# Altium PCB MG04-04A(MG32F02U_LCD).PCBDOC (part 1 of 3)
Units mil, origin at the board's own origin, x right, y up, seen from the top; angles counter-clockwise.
Board outline 5905.51 x 3543.31 mil, 2 copper layers (Top Layer, Bottom Layer); 293 components, 227 nets, 959 pads, 508 vias.
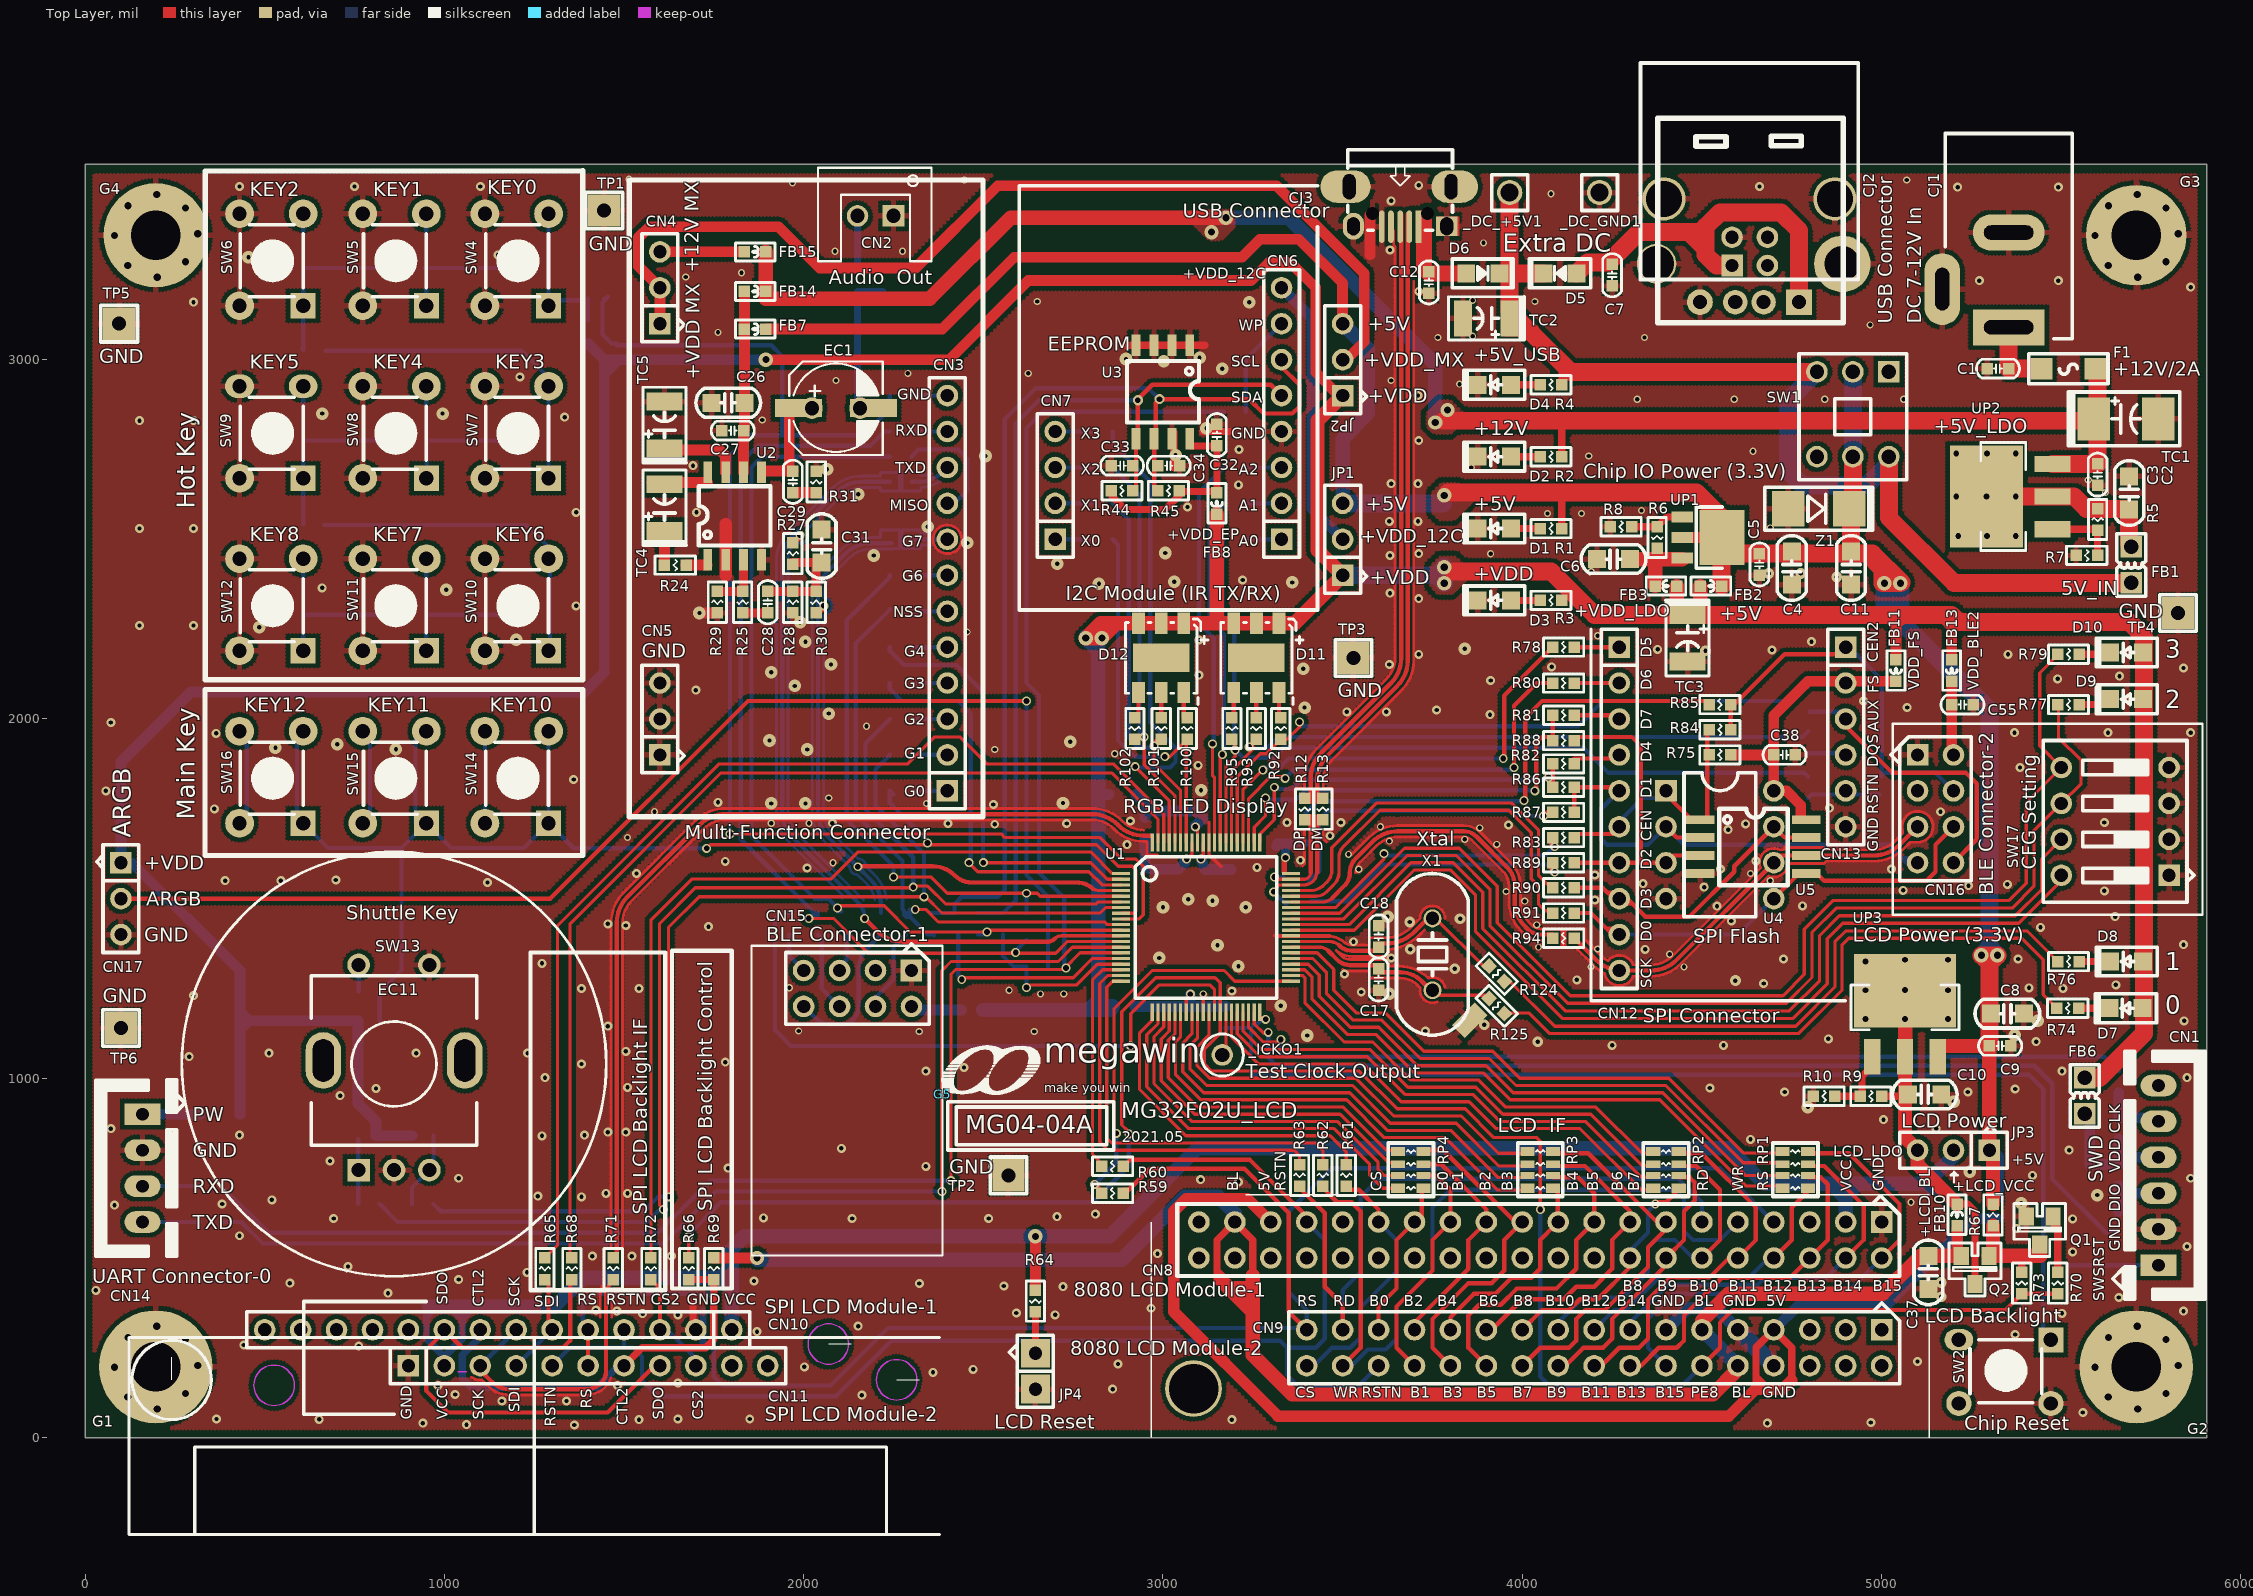
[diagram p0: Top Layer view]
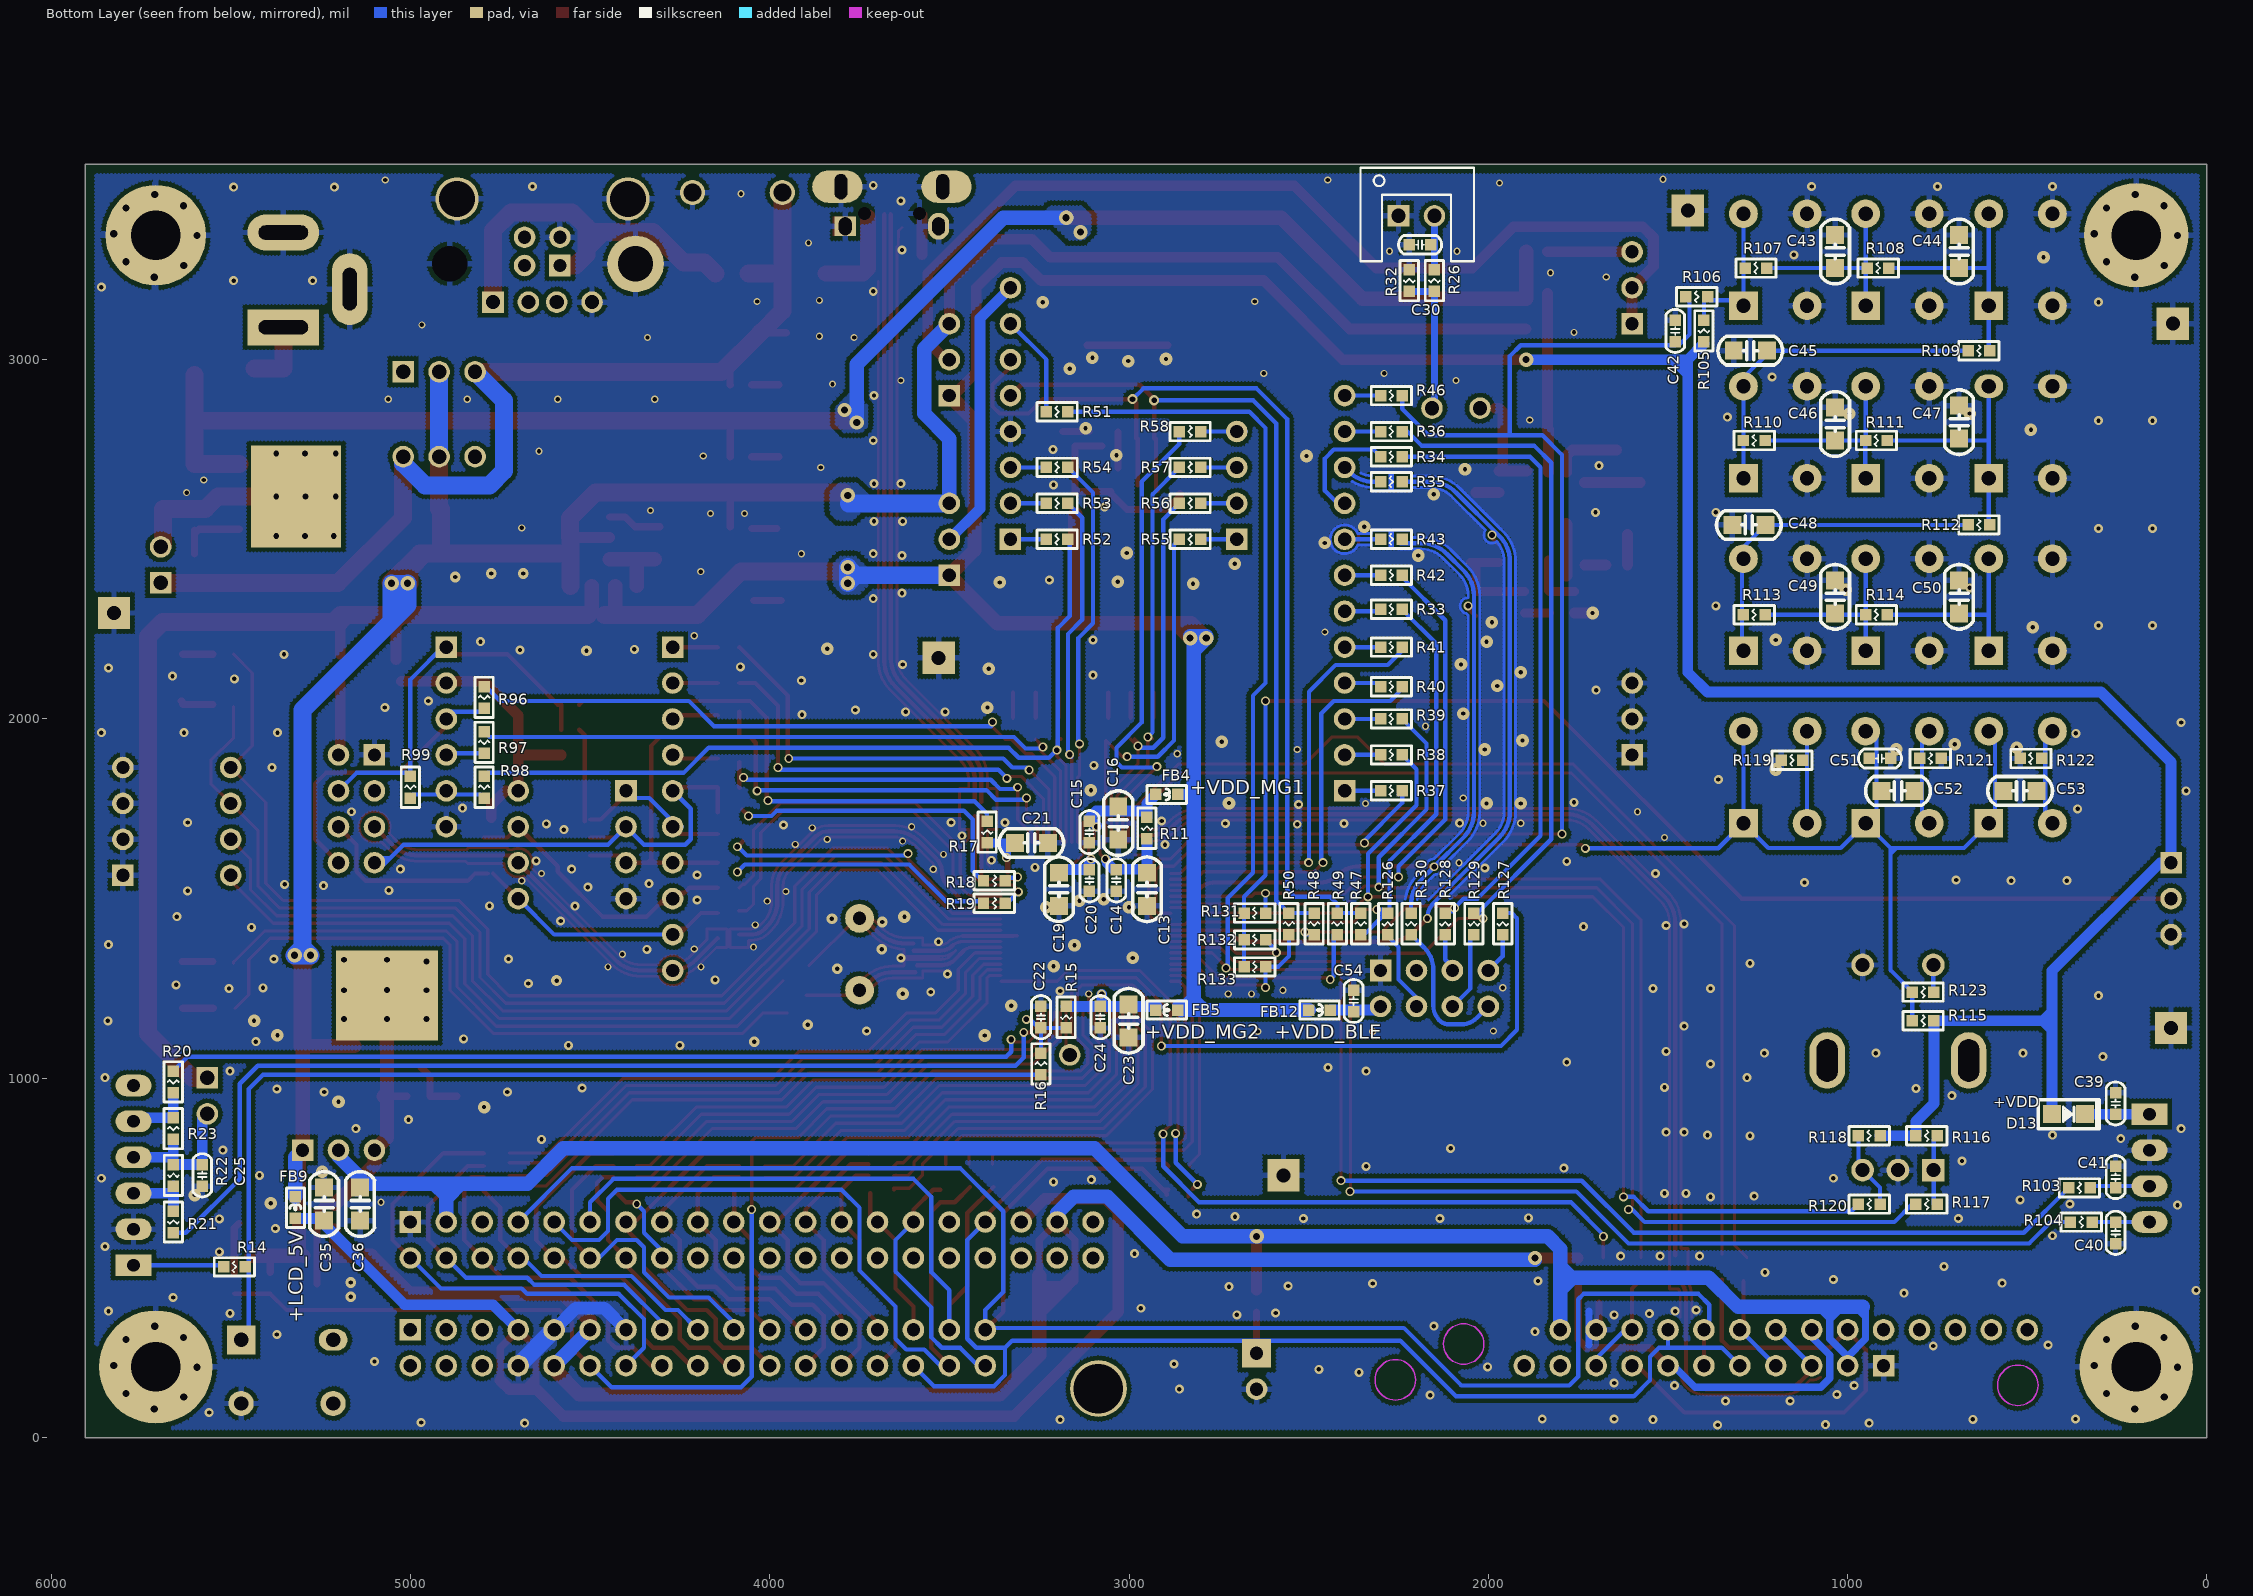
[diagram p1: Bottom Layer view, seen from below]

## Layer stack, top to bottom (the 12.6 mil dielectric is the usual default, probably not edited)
Top Layer: signal copper 1.4
Dielectric: dielectric 12.6, FR-4, Dk 4.8
Bottom Layer: signal copper 1.4

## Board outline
0,0 0,3543.31 5905.51,3543.31 5905.51,0

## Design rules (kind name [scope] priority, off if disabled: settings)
Clearance 12 [All] p1 off: gap=12
Clearance 7 [All] p2 off: gap=7
Clearance 6 [All] p3: gap=6
Height [All] p1: minheight=0 maxheight=5000 prefheight=500
HoleSize [All] p1: absolutevalues=TRUE maxlimit=500 minlimit=1 maxpercent=80.000 minpercent=20.000
PlaneConnect "Power Plane Connect Style - pads with no thermal_2" [(Name='CN3-39') Or (Name='CN3-40') Or (Name='CN4-2') Or (Name='CN4-3') Or (Name='CN4-4') Or (Name='CN4-6') Or (Name='CN6-3') Or (Name='CN6-4') Or (Name='CN8-1') Or (Name='CN8-2') Or (Name='CN8-3') Or (Name='CN8-4') Or (Name='CN8-5') Or (Name='CN8-6') Or (Name='CN8-7') Or (Name='CN8-8') Or (Name='CN8-9') Or (Name='CN8-10') Or (Name='CN8-11') Or (Name='CN8-12') Or (Name='CN8-13') Or (Name='CN8-14') Or (Name='CN8-15') Or (Name='CN8-16') Or (Name='CN9-1') Or (Name='CN9-2') Or (Name='CN9-3') Or (Name='CN9-4') Or (Name='CN9-5') Or (Name='CN9-6') Or (Name='CN9-7') Or (Name='CN9-8') Or (Name='CN9-9') Or (Name='CN9-10') Or (Name='CN9-11') Or (Name='CN9-12') Or (Name='CN9-13') Or (Name='CN9-14') Or (Name='CN9-15') Or (Name='CN9-16') Or (Name='SW1-1') Or (Name='SW1-4') Or (Name='SW2-3') Or (Name='SW2-4')] p1: planeconnectstyle=NoConnect reliefexpansion=20 reliefentries=4 reliefconductorwidth=10 reliefairgap=10 // PAD - No Thermal Connect Rule
PlaneConnect "Power Plane Connect Style - pads with no thermal" [(Name='CJ3-10') Or (Name='CJ3-11') Or (Name='CJ3-12') Or (Name='CJ3-13') Or (Name='CN1-6') Or (Name='CN10-1') Or (Name='CN10-2') Or (Name='CN10-3') Or (Name='CN10-4') Or (Name='CN10-5') Or (Name='CN10-6') Or (Name='CN10-7') Or (Name='CN10-8') Or (Name='CN10-9') Or (Name='CN10-10') Or (Name='CN10-11') Or (Name='CN10-12') Or (Name='CN10-13') Or (Name='CN10-14') Or (Name='CN10-15') Or (Name='CN10-16') Or (Name='CN11-1') Or (Name='CN11-2') Or (Name='CN11-3') Or (Name='CN11-4') Or (Name='CN11-5') Or (Name='CN11-6') Or (Name='CN11-7') Or (Name='CN11-8') Or (Name='CN11-9') Or (Name='CN11-10') Or (Name='CN11-11') Or (Name='CN11-12') Or (Name='CN11-13') Or (Name='CN11-14') Or (Name='CN11-15') Or (Name='CN11-16') Or (Name='CN3-3') Or (Name='CN3-16') Or (Name='CN3-20') Or (Name='CN3-29') Or (Name='CN3-30') Or (Name='CN3-31') Or (Name='CN3-32') Or (Name='CN3-33') Or (Name='CN3-34') Or (Name='CN3-35') Or (Name='CN3-36') Or (Name='CN3-37') Or (Name='CN3-38')] p2: planeconnectstyle=NoConnect reliefexpansion=20 reliefentries=4 reliefconductorwidth=10 reliefairgap=10 // PAD - No Thermal Connect Rule
PlaneConnect [All] p3: planeconnectstyle=Relief reliefexpansion=20 reliefentries=4 reliefconductorwidth=10 reliefairgap=10
PolygonConnect "LCD LDO" [InNet('+LCD_LDO')] p1: connectstyle=Direct reliefconductorwidth=10 reliefentries=4 polygonreliefangle="90 Angle"
PolygonConnect +5VLDO [InNet('+5V_LDO')] p2: connectstyle=Direct reliefconductorwidth=10 reliefentries=4 polygonreliefangle="90 Angle"
PolygonConnect VIA [ISVIA] p3: connectstyle=Direct reliefconductorwidth=10 reliefentries=4 polygonreliefangle="90 Angle"
PolygonConnect [All] p4: connectstyle=Relief reliefconductorwidth=15 reliefentries=4 polygonreliefangle="90 Angle"
RoomDefinition "06 Keys" [InComponentClass('06 Keys')] p1: confinementstyle=ConfineIn formatcopy=TRUE lockcomponents=FALSE outline -469,-447 6137,-447 6137,4157 -469,4157
RoomDefinition "05 SPI Flash and LED" [InComponentClass('05 SPI Flash and LED')] p2: confinementstyle=ConfineIn formatcopy=TRUE lockcomponents=FALSE outline -637,-726 6202,-726 6202,4105 -637,4105
RoomDefinition "04 LCD IF" [InComponentClass('04 LCD IF')] p3: confinementstyle=ConfineIn formatcopy=TRUE lockcomponents=FALSE outline -710,-425 6278,-425 6278,4053 -710,4053
RoomDefinition "03 Muti-Function IF" [InComponentClass('03 Muti-Function IF')] p4: confinementstyle=ConfineIn formatcopy=TRUE lockcomponents=FALSE outline -854,-770 6354,-770 6354,4005 -854,4005
RoomDefinition "02 MG32F02U_Main" [InComponentClass('02 MG32F02U_Main')] p5: confinementstyle=ConfineIn formatcopy=TRUE lockcomponents=FALSE outline -966,-770 6418,-770 6418,3932 -966,3932
RoomDefinition "01 Power Supply" [InComponentClass('01 Power Supply')] p6: confinementstyle=ConfineIn formatcopy=TRUE lockcomponents=FALSE outline -348,-495 6065,-495 6065,4225 -348,4225
RoutingVias [All] p1: holewidth=16 width=25 viastyle="Through Hole" minholewidth=16 minwidth=24 maxholewidth=40 maxwidth=50
SilkscreenOverComponentPads [All] p1: minsilkscreentomaskgap=10
SolderMaskExpansion [All] p1: expansion=4
Width [All] p1: maxlimit=200 minlimit=6 preferedwidth=10
24 further rules are at their usual default settings.

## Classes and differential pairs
component class "05 SPI Flash and LED": C38 C39 C40 C41 C55 CN12 CN13 CN14 CN16 D7 D8 D9 D10 D11 D12 D13 FB11 FB13 R74 R75 R76 R77 R78 R79 R80 R81 R82 R83 R84 R85 R86 R87 R88 R89 R90 R91 R92 R93 R94 R95 R96 R97 R98 R99 R100 R101 R102 R103 R104 SW17 U4 U5
component class "04 LCD IF": C35 C36 C37 CN8 CN9 CN10 CN11 FB9 FB10 JP3 JP4 Q1 Q2 R59 R60 R61 R62 R63 R64 R65 R66 R67 R68 R69 R70 R71 R72 R73 RP1 RP2 RP3 RP4
component class "03 Muti-Function IF": C26 C27 C28 C29 C30 C31 C32 C33 C34 C54 CN2 CN3 CN4 CN5 CN6 CN7 CN15 CN17 CN6666 EC1 FB7 FB8 FB12 FB14 FB15 JP1 JP2 R24 R25 R26 R27 R28 R29 R30 R31 R32 R33 R34 R35 R36 R37 R38 R39 R40 R41 R42 R43 R44 R45 R46 R47 R48 R49 R50 R51 R52 R53 R54 R55 R56 R57 R58 R126 R127 R128 R129 R130 R131 R132 R133 TC4 TC5 U2 U3
component class "01 Power Supply": _DC_+5V1 _DC_GND1 _DM1 _DP1 C1 C2 C3 C4 C5 C6 C7 C8 C9 C10 C11 C12 CJ1 CJ2 CJ3 CJ3111 D1 D2 D3 D4 D5 D6 F1 FB1 FB2 FB3 G1 G2 G3 G4 G5 R1 R2 R3 R4 R5 R6 R7 R8 R9 R10 SW1 TC1 TC2 TC3 TP1 TP2 TP3 TP4 TP5 TP6 UP1 UP2 UP3 Z1
component class "02 MG32F02U_Main": _ICKO1 _TS_PA13 _TS_PA14 _TS_PA15 _TS_PE9 C13 C14 C15 C16 C17 C18 C19 C20 C21 C22 C23 C24 C25 CN1 FB4 FB5 FB6 R11 R12 R13 R14 R15 R16 R17 R18 R19 R20 R21 R22 R23 R124 R125 SW2 U1 X1 X1000
component class "06 Keys": C42 C43 C44 C45 C46 C47 C48 C49 C50 C51 C52 C53 C56 D20 old-SW13 R105 R106 R107 R108 R109 R110 R111 R112 R113 R114 R115 R116 R117 R118 R119 R120 R121 R122 R123 SW4 SW5 SW6 SW7 SW8 SW9 SW10 SW11 SW12 SW13 SW14 SW15 SW16 SW19 SW20 SW21 SW13000 U6
net class MG_PA[0..15]: MG_PA0 MG_PA1 MG_PA2 MG_PA3 MG_PA4 MG_PA5 MG_PA6 MG_PA7 MG_PA8 MG_PA9 MG_PA10 MG_PA11 MG_PA12 MG_PA13 MG_PA14 MG_PA15
net class MG_PB[0..15]: MG_PB0 MG_PB1 MG_PB2 MG_PB3 MG_PB4 MG_PB5 MG_PB6 MG_PB7 MG_PB8 MG_PB9 MG_PB10 MG_PB11 MG_PB12 MG_PB13 MG_PB14 MG_PB15
net class MG_PC[0..14]: MG_PC0 MG_PC1 MG_PC2 MG_PC3 MG_PC4 MG_PC5 MG_PC6 MG_PC7 MG_PC8 MG_PC9 MG_PC10 MG_PC11 MG_PC12 MG_PC13 MG_PC14
net class MG_PD[0..15]: MG_PD0 MG_PD1 MG_PD2 MG_PD3 MG_PD4 MG_PD5 MG_PD6 MG_PD7 MG_PD8 MG_PD9 MG_PD10 MG_PD11 MG_PD12 MG_PD13 MG_PD14 MG_PD15
net class MG_PE[0..15]: MG_PE0 MG_PE1 MG_PE2 MG_PE3 MG_PE8 MG_PE9 MG_PE12 MG_PE13 MG_PE14 MG_PE15

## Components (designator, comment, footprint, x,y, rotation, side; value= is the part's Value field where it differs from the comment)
_DC_+5V1 "+5V_DC" SIP1-50 3965,3465 r0 top
_DC_GND1 "GND" SIP1-50 4215,3465 r0 top
_ICKO1 "TP-COIL" TPH60-COIL 3165,1065 r0 top
C1 "0.1uF" C-0603 5323.7,2975 r180 top
C2 "10uF/10v" C-0805 5689,2629 r90 top
C3 "1uF" C-0603 5601,2680 r270 top
C4 "10uF/10v" C-0805 4750,2420 r270 top
C5 "0.1uF" C-0603 4660,2430 r270 top
C6 "10uF/10v" C-0805 4254,2445 r180 top
C7 "1uF" C-0603 4250,3235 r270 top
C8 "10uF/10v" C-0805 5350,1180 r0 top
C9 "0.1uF" C-0603 5330,1090 r0 top
C10 "10uF/10v" C-0805 5120,955 r0 top
C11 "10uF/10v" C-0805 4915,2420 r270 top
C12 "1uF" C-0603 3740,3215 r270 top
C13 "10uF/10v" C-0805 2950,1526 r270 bottom
C14 "0.1uF" C-0603 3035,1551 r270 bottom
C15 "0.1uF" C-0603 3110,1685 r270 bottom
C16 "10uF/10v" C-0805 3030,1710 r270 bottom
C17 "10pF" C-0603 3600,1275 r270 top
C18 "10pF" C-0603 3600,1395 r90 top
C19 "4.7uF" C-0805 3195,1526 r270 bottom
C20 "0.1uF" C-0603 3110,1551 r270 bottom
C21 "4.7uF" C-0805 3271.81,1655 r180 bottom
C22 "4.7uF" C-0603 3245,1170 r90 bottom
C23 "10uF/10v" C-0805 3001.14,1160 r270 bottom
C24 "0.1uF" C-0603 3079.88,1170 r270 bottom
C25 "1uF" C-0603 5579.37,730 r270 bottom
C26 "10uF" C-0805 1790,2880 r180 top
C27 "0.1uF" C-0603 1802.71,2802.71 r180 top
C28 "1uF" C-0603 1900,2325 r90 top
C29 "0.047uF" C-0603 1970,2660 r270 top
C30 "1000pF" C-0603 2190,3320 r0 bottom
C31 "4.7uF" C-0805 2050,2481 r90 top
C32 "1uF" C-0603 3150,2790 r90 top
C33 "47PF" C-0603 2886,2705 r180 top
C34 "47PF" C-0603 3016,2705 r0 top
C35 "10uF/10v" C-0805 5240,650 r90 bottom
C36 "10uF/10v" C-0805 5140,650 r270 bottom
C37 "10uF/10v" C-0805 5130,460 r270 top
C38 "1uF" C-0603 4730,1900 r0 top
C39 "0.1uF" C-0603 254.49,930 r90 bottom
C40 "47PF" C-0603 254.49,570 r270 bottom
C41 "47PF" C-0603 254.49,725 r90 bottom
C42 "0.1uF" C-0603 1480,3080 r90 bottom
C43 "0.1uF" C-0805 1035,3301 r90 bottom
C44 "0.1uF" C-0805 690,3301 r90 bottom
C45 "0.1uF" C-0805 1271,3025 r0 bottom
C46 "0.1uF" C-0805 1035,2821 r90 bottom
C47 "0.1uF" C-0805 690,2826 r90 bottom
C48 "0.1uF" C-0805 1275,2540 r0 bottom
C49 "0.1uF" C-0805 1035,2340 r90 bottom
C50 "0.1uF" C-0805 690,2340 r90 bottom
C51 "0.1uF" C-0603 910,1890 r180 bottom
C52 "0.1uF" C-0805 860,1800 r180 bottom
C53 "0.1uF" C-0805 520,1800 r180 bottom
C54 "1uF" C-0603 2375,1215 r90 bottom
C55 "1uF" C-0603 5225,2040 r0 top
CJ1 "POWER_JACK" JACK-DC-TC18013 5353.7,3629.37 r180 top locked
CJ2 "CJ-USB-AB" CON_USB-AB 4770,3160 r180 top locked
CJ3 "CJ-USB-Micro" USB5-MICRO-7.5.X5.4P065 3711.18,3370 r180 top
CN1 "SIP6-2.54mm" HD6-P2.54-UL 5770.63,730 r90 top
CN2 "SIP2-2.54" SIP2-2.54 2200,3400 r0 top locked
CN3 "HEADER12" SIP12-P2.54 2400,1800 r90 top locked
CN4 "HEADER_3" SIP3-P2.54 1600,3100 r90 top
CN5 "HEADER_3" SIP3-P2.54 1600,1900 r90 top
CN6 "HEADER8-2.54-Female" SIP8-P2.54 3330,2500 r90 top locked
CN7 "HEADER4-2.54-Female" SIP4-P2.54 2700,2500 r90 top
CN8 "HEADER20X2-2.54-Female" HD20X2A-P2.54 5000,600 r180 top locked
CN9 "HEADER17X2-2.54-Female" HD17X2-P2.54 5000,300 r180 top locked
CN10 "HEADER14-2.54-Female" SIP14-P2.54-SPI_LCD 1800,300 r180 top locked
CN11 "HEADER11-2.54-Female" SIP11-P2.54-SPI_LCD 1700,200 r0 top locked
CN12 "HEADER10" SIP10-P2.54 4270,2200 r270 top locked
CN13 "HEADER6" SIP6-P2.54 4899.92,2200 r270 top
CN14 "SIP4-2.54mm" HD4-P2.54-Z12.4X5.7X7-UL 160,750 r270 top
CN15 "HEADER4X2-Female" HD4X2-P2.54 2300,1300 r180 top locked
CN16 "HEADER4X2-Female" HD4X2-P2.54 5100,1900 r270 top
CN17 "HEADER_3" SIP3-P2.54 100,1600 r270 top
D1 "LED0805-Green" LED-0805 3920,2530.01 r270 top
D2 "LED0805-Yellow" LED-0805 3920,2730 r270 top
D3 "LED0805-Red" LED-0805 3920,2330.01 r270 top
D4 "LED0805-Green" LED-0805 3920,2929.99 r270 top
D5 "B5817" D-0805 4105,3240 r270 top
D6 "B5817" D-0805 3890,3240 r90 top
D7 "LED0805-Green" LED-0805 5678,1195 r270 top
D8 "LED0805-Green" LED-0805 5680,1325 r270 top
D9 "LED0805-Green" LED-0805 5680,2055 r270 top
D10 "LED0805-Green" LED-0805 5680,2185 r270 top
D11 "LED-6P-RGB" LED-6P-RGB-50X50 3260,2170 r270 top locked
D12 "LED-6P-RGB" LED-6P-RGB-50X50 2995,2170 r270 top locked
D13 "B5817" D-0805 385,900 r90 bottom
EC1 "100uF-EC/25v" C-EC-S-P7.2-T6.3X5.5 2090,2865 r0 top locked
F1 "FUSE/3A" FUSE-1206 5445,2975 r90 top
FB1 "FB" L0805+DIP 5695,2430 r270 top
FB2 "FB_0603" L-0603 4525,2370 r180 top
FB3 "FB_0603" L-0603 4400,2370 r0 top
FB4 "FB_0603" L-0603 2895,1790 r0 bottom
FB5 "FB_0603" L-0603 2895,1190 r180 bottom
FB6 "FB" L0805+DIP 5565,950 r90 top
FB7 "FB_0603" L-0603 1865,3085 r180 top
FB8 "FB_0603" L-0603 3150,2600 r90 top
FB9 "FB_0603" L-0603 5320,640 r270 bottom
FB10 "FB_0603" L-0603 5210,620 r270 top
FB11 "FB_0603" L-0603 5040,2135 r90 top
FB12 "FB_0603" L-0603 2470,1190 r0 bottom
FB13 "FB_0603" L-0603 5195,2135 r90 top
FB14 "FB_0603" L-0603 1865,3190 r180 top
FB15 "FB_0603" L-0603 1865,3300 r180 top
G1 "3_5mm_8via" SCREW9-H3.5-R8#1 196.85,196.85 r0 top
G2 "3_5mm_8via" SCREW9-H3.5-R8#1 5708.66,196.85 r0 top
G3 "3_5mm_8via" SCREW9-H3.5-R8#2 5708.66,3346.46 r0 top
G4 "3_5mm_8via" SCREW9-H3.5-R8#3 196.85,3346.46 r0 top
G5 "Logo_Megawin_3_4" MEGAWIN_3.4 2386.61,955 r0 top
JP1 "HEADER_3" SIP3-P2.54 3500,2400 r90 top
JP2 "HEADER_3" SIP3-P2.54 3500,2900 r90 top
JP3 "HEADER_3" SIP3-P2.54 5300,800 r180 top
JP4 "JUMPER" SIP2-P2.54-JUMPER 2645,235 r270 top
Q1 "2N3904" SOT-23#1 5440,580 r0 top
Q2 "2302N" SOT-23#2 5260,470 r0 top
R1 "3K" R-0603 4080,2530 r180 top
R2 "4.7K" R-0603 4080,2730 r180 top
R3 "3K" R-0603 4080,2330 r180 top
R4 "3K" R-0603 4080,2930 r180 top
R5 "150" R-0603 5601,2555 r270 top
R6 "180" R-0603 4375,2505 r90 top
R7 "470" R-0603 5571,2455 r180 top
R8 "300" R-0603 4275,2535 r180 top
R9 "180" R-0603 4970,950 r180 top
R10 "300" R-0603 4840,950 r180 top
R11 "0" R-0603 2950,1696 r90 bottom
R12 "0" R-0603 3394.41,1749.24 r90 top
R13 "0" R-0603 3444.41,1749.24 r90 top
R14 "22" R-0603 5490,475 r180 bottom
R15 "47K" R-0603 3175.12,1170 r90 bottom
R16 "22" R-0603 3245,1040 r270 bottom
R17 "0" R-0603 3395,1685 r90 bottom
R18 "0" R-0603 3375,1550 r0 bottom
R19 "0" R-0603 3375,1487.36 r0 bottom
R20 "22" R-0603 5660,990 r270 bottom
R21 "22" R-0603 5659.37,600 r90 bottom
R22 "10K" R-0603 5659.37,730 r90 bottom
R23 "10K" R-0603 5660,860 r270 bottom
R24 "1.2K" R-0603 1642.71,2428.24 r180 top
R25 "4.7K" R-0603 1830,2325 r90 top
R26 "10" R-0603 2150,3220 r90 bottom
R27 "0" R-0603 1970,2460 r270 top
R28 "10K" R-0603 1970,2325 r270 top
R29 "470" R-0603 1760,2325 r270 top
R30 "100" R-0603 2035,2325 r90 top
R31 "10" R-0603 2035,2660 r90 top
R32 "1K" R-0603 2220,3220 r90 bottom
R33 "22" R-0603 2270,2305 r180 bottom
R34 "22" R-0603 2270,2730 r180 bottom
R35 "22" R-0603 2270,2660 r180 bottom
R36 "22" R-0603 2270,2800 r180 bottom
R37 "22" R-0603 2270,1800 r180 bottom
R38 "22" R-0603 2270,1900 r180 bottom
R39 "22" R-0603 2270,2000 r180 bottom
R40 "0" R-0603 2270,2090 r180 bottom
R41 "0" R-0603 2270,2200 r180 bottom
R42 "0" R-0603 2270,2400 r180 bottom
R43 "0" R-0603 2270,2500 r180 bottom
R44 "10K" R-0603 2886,2635 r0 top
R45 "10K" R-0603 3015,2635 r180 top
R46 "0" R-0603 2270,2900 r180 bottom
R47 "22" R-0603 2355,1430 r270 bottom
R48 "22" R-0603 2485,1430 r270 bottom
R49 "22" R-0603 2420,1430 r270 bottom
R50 "22" R-0603 2555,1430 r270 bottom
R51 "22" R-0603 3200,2855 r180 bottom
R52 "22" R-0603 3200,2500 r180 bottom
R53 "22" R-0603 3200,2600 r180 bottom
R54 "22" R-0603 3200,2700 r180 bottom
R55 "0" R-0603 2830,2500 r0 bottom
R56 "0" R-0603 2830,2600 r0 bottom
R57 "0" R-0603 2830,2700 r0 bottom
R58 "0" R-0603 2830,2800 r0 bottom
R59 "22" R-0603 2860,755 r0 top
R60 "22" R-0603 2860,680 r0 top
R61 "22" R-0603 3510,730 r270 top
R62 "22" R-0603 3445,730 r270 top
R63 "22" R-0603 3380,730 r270 top
R64 "47K" R-0603 2645,380 r90 top
R65 "22" R-0603 1280,470 r270 top
R66 "10" R-0603 1680,470 r270 top
R67 "1K" R-0603 5310,620 r90 top
R68 "22" R-0603 1355,470 r270 top
R69 "0" R-0603 1750,470 r270 top
R70 "100" R-0603 5490,430 r90 top
R71 "22" R-0603 1470,470 r270 top
R72 "22" R-0603 1575,470 r270 top
R73 "100" R-0603 5390,430 r90 top
R74 "1K" R-0603 5518,1195 r180 top
R75 "47K" R-0603 4550,1900 r180 top
R76 "1K" R-0603 5520,1325 r180 top
R77 "1K" R-0603 5520,2040 r180 top
R78 "22" R-0603 4115,2200 r0 top
R79 "1K" R-0603 5520,2180 r180 top
R80 "22" R-0603 4115,2100 r0 top
R81 "22" R-0603 4115,2010 r0 top
R82 "22" R-0603 4115,1875 r0 top
R83 "22" R-0603 4115,1670 r0 top
R84 "0" R-0603 4550,1970 r180 top
R85 "22" R-0603 4550,2040 r0 top
R86 "22" R-0603 4115,1810 r0 top
R87 "22" R-0603 4115,1740 r0 top
R88 "22" R-0603 4115,1940 r0 top
R89 "22" R-0603 4115,1600 r0 top
R90 "22" R-0603 4115,1530 r0 top
R91 "22" R-0603 4115,1460 r0 top
R92 "1K" R-0603 3328,1973.54 r270 top
R93 "1K" R-0603 3260,1973.54 r270 top
R94 "22" R-0603 4115,1390 r0 top
R95 "1K" R-0603 3192,1973.54 r270 top
R96 "22" R-0603 4795,2060 r270 bottom
R97 "22" R-0603 4795,1935 r270 bottom
R98 "22" R-0603 4795,1810 r270 bottom
R99 "0" R-0603 5000,1810 r270 bottom
R100 "1K" R-0603 3067.99,1973.54 r270 top
R101 "1K" R-0603 2995,1973.54 r270 top
R102 "1K" R-0603 2922.01,1973.54 r270 top
R103 "22" R-0603 355,695 r0 bottom
R104 "22" R-0603 350,600 r0 bottom
R105 "2.2K" R-0603 1400,3080 r90 bottom
R106 "0" R-0603 1420,3175 r180 bottom
R107 "270" R-0603 1255,3255 r180 bottom
R108 "360" R-0603 915,3255 r180 bottom
R109 "470" R-0603 635,3025 r0 bottom
R110 "680" R-0603 1260,2775 r180 bottom
R111 "1K" R-0603 920,2775 r180 bottom
R112 "1.8K" R-0603 635,2540 r0 bottom
R113 "3.3k" R-0603 1260,2290 r180 bottom
R114 "12K" R-0603 920,2290 r180 bottom
R115 "2.2K" R-0603 790,1160 r0 bottom
R116 "2.2K" R-0603 780,840 r0 bottom
R117 "22" R-0603 780,650 r0 bottom
R118 "2.2K" R-0603 940,840 r180 bottom
R119 "2.2K" R-0603 1155,1885 r180 bottom
R120 "22" R-0603 940,650 r0 bottom
R121 "4.7K" R-0603 770,1890 r0 bottom
R122 "12K" R-0603 490,1890 r180 bottom
R123 "10" R-0603 790,1240 r0 bottom
R124 "0" R-0603 3928.89,1291.11 r315 top
R125 "0" R-0603 3928.89,1201.11 r315 top
R126 "22" R-0603 2280,1430 r90 bottom
R127 "22" R-0603 1960,1430 r90 bottom
R128 "22" R-0603 2120,1430 r90 bottom
R129 "22" R-0603 2040,1430 r90 bottom
R130 "22" R-0603 2215,1430 r90 bottom
R131 "22" R-0603 2650,1460 r180 bottom
R132 "22" R-0603 2650,1385 r180 bottom
R133 "22" R-0603 2650,1310 r180 bottom
RP1 "RP22X4" RP-0603 4760,745 r270 top
RP2 "RP22X4" RP-0603 4400,745 r270 top
RP3 "RP22X4" RP-0603 4050,745 r270 top
RP4 "RP22X4" RP-0603 3690,745 r270 top
SW1 "SW_6P" SW6-P2.54-Z8X8X12.5 5020,2966.22 r180 top
SW2 "SW1_4P" SW-TACT-P4.5X6.5-Z6.2X6.2X5#1 5471,272 r180 top
SW4 "SW1_4P" SW-TACT-P4.5X6.5-Z6.2X6.2X5#2 1290,3150 r90 top locked
SW5 "SW1_4P" SW-TACT-P4.5X6.5-Z6.2X6.2X5#2 950,3150 r90 top locked
SW6 "SW1_4P" SW-TACT-P4.5X6.5-Z6.2X6.2X5#2 607,3150 r90 top locked
SW7 "SW1_4P" SW-TACT-P4.5X6.5-Z6.2X6.2X5#2 1290,2670 r90 top locked
SW8 "SW1_4P" SW-TACT-P4.5X6.5-Z6.2X6.2X5#2 950,2670 r90 top locked
SW9 "SW1_4P" SW-TACT-P4.5X6.5-Z6.2X6.2X5#3 607,2670 r90 top
SW10 "SW1_4P" SW-TACT-P4.5X6.5-Z6.2X6.2X5#2 1290,2190 r90 top locked
SW11 "SW1_4P" SW-TACT-P4.5X6.5-Z6.2X6.2X5#2 950,2190 r90 top locked
SW12 "SW1_4P" SW-TACT-P4.5X6.5-Z6.2X6.2X5#2 607,2190 r90 top locked
SW13 "EC11_SW" SW5P_EC11 860,1039.84 r0 top locked
SW14 "SW1_4P" SW-TACT-P4.5X6.5-Z6.2X6.2X5#2 1290,1710 r90 top
SW15 "SW1_4P" SW-TACT-P4.5X6.5-Z6.2X6.2X5#2 950,1710 r90 top locked
SW16 "SW1_4P" SW-TACT-P4.5X6.5-Z6.2X6.2X5#2 607,1710 r90 top
SW17 "SW_DIP-4" SW-DIP4 5800,1565 r90 top
TC1 "10uF/25V" C-1812+ 5680,2835 r90 top
TC2 "47uF/10V" C-1210+ 3900,3115 r180 top
TC3 "47uF/10V" C-1210+ 4460,2225 r270 top
TC4 "10uF/10v" C-1210+ 1612.71,2588.24 r90 top
TC5 "10uF/10v" C-1210+ 1612.71,2818.24 r90 top
TP1 "TP-Gold" SIP1-39 1445,3415 r90 top
TP2 "TP-Gold" SIP1-39 2570,730 r90 top
TP3 "TP-Gold" SIP1-39 3530,2170 r90 top
TP4 "TP-Gold" SIP1-39 5825,2295 r90 top
TP5 "TP-Gold" SIP1-39 95,3100 r90 top
TP6 "TP-Gold" SIP1-39 100,1140 r90 top
U1 "MG32F02U_LQFP80" QFP80-P0.4-Z12X12 3120,1420 r270 top locked
U2 "IC-LM386" SOP8-P1.27-W6.2 1732.71,2442.65 r0 top
U3 "24C16-SOP" SOP8-P1.27-W6.604 3075,3040 r180 top
U4 "EN25T80-DIP" DIP8-P2.54-W7.62 4400,1800 r270 top
U5 "MX25LXX-SOP" SOP8-P1.27-W6.2+8.1 4495,1720 r270 top
UP1 "AP1115B-ADJ" SOT-89-1 4517,2505 r270 top
UP2 "AP1117-ADJ" SOT223H\3P#1 5348,2619 r90 top
UP3 "AP1117-ADJ" SOT223H\3P#2 5065,1188 r0 top
X1 "24MHz" XTAL-HC49US-G2 3750,1445 r270 top
Z1 "Zener-5.1V" D-5819-1 4725,2585 r270 top

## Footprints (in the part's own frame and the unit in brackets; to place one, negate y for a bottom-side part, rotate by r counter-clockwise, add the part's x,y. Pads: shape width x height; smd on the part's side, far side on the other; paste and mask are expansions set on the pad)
C-0603 [mil]
  rect 32x32 smd: 1(-30,0) 2(30,0)
  silkscreen extent -60,-26 60,26
C-0805 [mil]
  rect 50x50 smd: 1(-46,0) 2(46,0)
  silkscreen extent -90,-40 90,40
C-1210+ [mil]
  rect 50x100 smd: 1(-65,0) 2(65,0)
  silkscreen extent -105,-60 105,60
C-1812+ [mil]
  rect 120x90 smd: 1(0,90) 2(0,-90)
  silkscreen extent -75,-150 75,160
C-EC-S-P7.2-T6.3X5.5 [mil]
  rect 129.92x50 smd: 1(-104.33,0) 2(104.33,0)
  round 60 hole 40: 1(-66.93,0) 2(66.93,0)
  silkscreen extent -130,-130 130,130
CON_USB-AB [mm]
  rect 1.824x1.824 / inner round 1.524 / far side rect 1.524x1.524 hole 1: 1(0,0)
  round 1.724 / inner round 1.524 / far side round 1.524 hole 1: 2(2.5,0) 3(4.5,0)
  round 1.824 / inner round 1.524 / far side round 1.524 hole 1: 4(7,0)
  round 4 / inner round 1.524 / far side round 1.524 hole 2.5: 5(-3.07,-2.71)
  round 2.794 / inner round 1.524 / far side round 4 hole 2.5: 6(10.07,-2.71)
  rect 1.524x1.524 hole 0.94: 7(4.73,-2.59)
  round 1.524 hole 0.94: 8(2.23,-2.59) 9(2.23,-4.59) 10(4.73,-4.59)
  round 3.048 hole 2.54: 11(-2.54,-7.3) 12(9.54,-7.3)
  silkscreen extent -4.2,-16.91 11.2,1.46
D-0805 [mil]
  rect 50x50 smd: 1(0,46) 2(0,-46)
  silkscreen extent -40,-85 40,85
D-5819-1 [mil]
  rect 100x90 smd: 1(0,15) 2(0,185)
  silkscreen extent -60,-50 60,250
DIP8-P2.54-W7.62 [mil]
  rect 60x60 hole 37: 1(0,0)
  round 60 hole 37: 2(100,0) 3(200,0) 4(300,0) 5(300,300) 6(200,300) 7(100,300) 8(0,300)
  silkscreen extent -50,50 350,250
FUSE-1206 [mil]
  rect 60x60 smd: 1(0,0) 2(0,-150)
  silkscreen extent -42,-185 41,35
HD4-P2.54-Z12.4X5.7X7-UL [mil]
  rect 60x100 hole 35: 1(-150,0)
  oval 60x100 hole 35: 2(-50,0) 3(50,0) 4(150,0)
  silkscreen extent -246,-130 245,118
HD4X2-P2.54 [mil]
  rect 60x60 hole 37: 1(0,0)
  round 60 hole 37: 2(0,100) 3(100,0) 4(100,100) 5(200,0) 6(200,100) 7(300,0) 8(300,100)
  silkscreen extent -87,-75 445,793
HD6-P2.54-UL [mil]
  rect 60x100 hole 35: 1(-250,0)
  oval 60x100 hole 35: 2(-150,0) 3(-50,0) 4(50,0) 5(150,0) 6(250,0)
  silkscreen extent -344,-130 346,127
HD17X2-P2.54 [mil]
  rect 60x60 hole 37: 1(0,0)
  round 60 hole 37: 2(0,100) 3(100,0) 4(100,100) 5(200,0) 6(200,100) 7(300,0) 8(300,100) 9(400,0) 10(400,100) 11(500,0) 12(500,100) 13(600,0) 14(600,100) 15(700,0) 16(700,100) 17(800,0) 18(800,100) 19(900,0) 20(900,100) 21(1000,0) 22(1000,100) 23(1100,0) 24(1100,100) 25(1200,0) 26(1200,100) 27(1300,0) 28(1300,100) 29(1400,0) 30(1400,100) 31(1500,0) 32(1500,100) 33(1600,0) 34(1600,100)
  silkscreen extent -50,-75 1650,150
HD20X2A-P2.54 [mil]
  rect 60x60 hole 37: 1(0,0)
  round 60 hole 37: 2(100,0) 3(200,0) 4(300,0) 5(400,0) 6(500,0) 7(600,0) 8(700,0) 9(800,0) 10(900,0) 11(1000,0) 12(1100,0) 13(1200,0) 14(1300,0) 15(1400,0) 16(1500,0) 17(1600,0) 18(1700,0) 19(1800,0) 20(1900,0) 21(0,100) 22(100,100) 23(200,100) 24(300,100) 25(400,100) 26(500,100) 27(600,100) 28(700,100) 29(800,100) 30(900,100) 31(1000,100) 32(1100,100) 33(1200,100) 34(1300,100) 35(1400,100) 36(1500,100) 37(1600,100) 38(1700,100) 39(1800,100) 40(1900,100)
  silkscreen extent -133,-76 2033,600
JACK-DC-TC18013 [mm]
  rect 5.08x2.54 hole 1 slot 3.5 at 0 deg: 1(0,13.7)
  oval 2.54x5.08 hole 1 slot 3 at 90 deg: 2(4.7,11)
  oval 5.08x2.54 hole 1 slot 3.5 at 0 deg: 3(0,7)
  silkscreen extent -4.5,0 4.5,14.5
L0805+DIP [mil]
  rect 60x60 / inner round 60 / far side round 60 hole 40: 1(-49,0)
  rect 60x60 hole 40: 2(51,0)
  silkscreen extent -86,-40 88,40
L-0603 [mil]
  rect 32x32 smd: 1(-30,0) 2(30,0)
  silkscreen extent -55,-25 55,25
LED-6P-RGB-50X50 [mm]
  rect 2x4 smd: 0(0,0)
  rect 1.5x0.9 smd: 1(-2.45,1.6) 2(2.45,1.6) 3(-2.45,0) 4(2.45,0) 5(-2.45,-1.6) 6(2.45,-1.6)
  silkscreen extent -2.76,-2.52 3.3,3.3
LED-0805 [mil]
  rect 50x50 smd: 1(0,48) 2(0,-44)
  silkscreen extent -40,-83 40,87
MEGAWIN_3.4 [mil]
  silkscreen extent -2,0 272,135
QFP80-P0.4-Z12X12 [mm]
  rect 0.229x1.27 smd: 1(-3.8,-6) 2(-3.4,-6) 3(-3,-6) 4(-2.6,-6) 5(-2.2,-6) 6(-1.8,-6) 7(-1.4,-6) 8(-1,-6) 9(-0.6,-6) 10(-0.2,-6) 11(0.2,-6) 12(0.6,-6) 13(1,-6) 14(1.4,-6) 15(1.8,-6) 16(2.2,-6) 17(2.6,-6) 18(3,-6) 19(3.4,-6) 20(3.8,-6) 41(3.8,6) 42(3.4,6) 43(3,6) 44(2.6,6) 45(2.2,6) 46(1.8,6) 47(1.4,6) 48(1,6) 49(0.6,6) 50(0.2,6) 51(-0.2,6) 52(-0.6,6) 53(-1,6) 54(-1.4,6) 55(-1.8,6) 56(-2.2,6) 57(-2.6,6) 58(-3,6) 59(-3.4,6) 60(-3.8,6)
  rect 1.27x0.229 smd: 21(6,-3.8) 22(6,-3.4) 23(6,-3) 24(6,-2.6) 25(6,-2.2) 26(6,-1.8) 27(6,-1.4) 28(6,-1) 29(6,-0.6) 30(6,-0.2) 31(6,0.2) 32(6,0.6) 33(6,1) 34(6,1.4) 35(6,1.8) 36(6,2.2) 37(6,2.6) 38(6,3) 39(6,3.4) 40(6,3.8) 61(-6,3.8) 62(-6,3.4) 63(-6,3) 64(-6,2.6) 65(-6,2.2) 66(-6,1.8) 67(-6,1.4) 68(-6,1) 69(-6,0.6) 70(-6,0.2) 71(-6,-0.2) 72(-6,-0.6) 73(-6,-1) 74(-6,-1.4) 75(-6,-1.8) 76(-6,-2.2) 77(-6,-2.6) 78(-6,-3) 79(-6,-3.4) 80(-6,-3.8)
  silkscreen extent -5,-5 5,5
R-0603 [mil]
  rect 32x32 smd: 1(-30,0) 2(30,0)
  silkscreen extent -56,-26 56,26
RP-0603 [mm]
  rect 0.65x1 smd: 1(-1.3,-0.9) 4(1.3,-0.9) 5(1.3,0.9) 8(-1.3,0.9)
  rect 0.5x1 smd: 2(-0.4,-0.9) 3(0.4,-0.9) 6(0.4,0.9) 7(-0.4,0.9)
  silkscreen extent -1.9,-1.6 1.9,1.6
SCREW9-H3.5-R8#1 [mil]
  round 315 hole 138: 1(0,0)
  round 40 hole 20: 2(3,113) 3(-115,-1) 4(117,4) 5(4,-117) 6(83,76) 7(-77,82) 8(-78,-84) 9(83,-74)
SCREW9-H3.5-R8#2 [mil]
  round 280 hole 138: 1(0,0)
  round 40 hole 20: 2(3,113) 3(-115,-1) 4(117,4) 5(4,-117) 6(83,76) 7(-77,82) 8(-78,-84) 9(83,-74)
SCREW9-H3.5-R8#3 [mil]
  round 290 hole 138: 1(0,0)
  round 40 hole 20: 2(3,113) 3(-115,-1) 4(117,4) 5(4,-117) 6(83,76) 7(-77,82) 8(-78,-84) 9(83,-74)
SIP1-39 [mil]
  rect 90x90 hole 39: 1(0,0)
  silkscreen extent -51,-51 51,51
SIP1-50 [mil]
  round 70 hole 50: 1(0,0)
  silkscreen extent -50,-50 50,50
SIP2-2.54 [mil]
  rect 60x60 hole 40: 1(50,0)
  round 60 hole 40: 2(-50,0)
  silkscreen extent -160,-126 156,134
SIP2-P2.54-JUMPER [mil]
  rect 80x80 hole 37: 1(0,0)
  rect 80x80 / inner round 60 / far side round 60 hole 37: 2(100,0)
  silkscreen extent -50,-72 150,50
SIP3-P2.54 [mil]
  rect 60x60 hole 37: 1(0,0)
  round 60 hole 37: 2(100,0) 3(200,0)
  silkscreen extent -50,-68 250,50
SIP4-P2.54 [mil]
  rect 60x60 hole 37: 1(0,0)
  round 60 hole 37: 2(100,0) 3(200,0) 4(300,0)
  silkscreen extent -50,-50 350,50
SIP6-P2.54 [mil]
  rect 60x60 hole 37: 1(0,0)
  round 60 hole 37: 2(100,0) 3(200,0) 4(300,0) 5(400,0) 6(500,0)
  silkscreen extent -50,-50 550,50
SIP8-P2.54 [mil]
  rect 60x60 hole 37: 1(0,0)
  round 60 hole 37: 2(100,0) 3(200,0) 4(300,0) 5(400,0) 6(500,0) 7(600,0) 8(700,0)
  silkscreen extent -50,-50 750,50
SIP10-P2.54 [mil]
  rect 60x60 hole 37: 1(0,0)
  round 60 hole 37: 2(100,0) 3(200,0) 4(300,0) 5(400,0) 6(500,0) 7(600,0) 8(700,0) 9(800,0) 10(900,0)
  silkscreen extent -50,-79 984,629
SIP11-P2.54-SPI_LCD [mil]
  rect 60x60 hole 37: 1(-800,0)
  round 60 hole 37: 2(-700,0) 3(-600,0) 4(-500,0) 5(-400,0) 6(-300,0) 7(-200,0) 8(-100,0) 9(0,0) 10(100,0) 11(200,0)
  silkscreen extent -1577,-470 677,79
SIP12-P2.54 [mil]
  rect 60x60 hole 37: 1(0,0)
  round 60 hole 37: 2(100,0) 3(200,0) 4(300,0) 5(400,0) 6(500,0) 7(600,0) 8(700,0) 9(800,0) 10(900,0) 11(1000,0) 12(1100,0)
  silkscreen extent -72,-99 1700,885
SIP14-P2.54-SPI_LCD [mil]
  round 60 hole 37: 1(0,0) 2(100,0) 3(200,0) 4(300,0) 5(400,0) 6(500,0) 7(600,0) 8(700,0) 9(800,0) 10(900,0) 11(1000,0) 12(1100,0) 13(1200,0) 14(1300,0)
  silkscreen extent -332,-79 1350,235
SOP8-P1.27-W6.2 [mil]
  rect 24x60 smd: 1(0,0) 2(50,0) 3(100,0) 4(150,0) 5(150,244) 6(100,244) 7(50,244) 8(0,244)
  silkscreen extent -25,40 175,205
SOP8-P1.27-W6.2+8.1 [mil]
  rect 24x80 smd: 1(0,0) 2(50,0) 3(100,0) 4(150,0) 5(150,295.28) 6(100,295.28) 7(50,295.28) 8(0,295.28)
  silkscreen extent -30,53 183,244
SOP8-P1.27-W6.604 [mil]
  rect 24x60 smd: 1(0,0) 2(50,0) 3(100,0) 4(150,0) 5(150,260) 6(100,260) 7(50,260) 8(0,260)
  silkscreen extent -25,44 175,215
SOT223H\3P#1 [mil]
  rect 45x100 smd: 1(-91,-128) 2(0,-128) 3(91,-128)
  rect 283x204 smd: 4(0,56)
  rect 283x250 smd far side: 4(0,30)
  silkscreen extent -150,-53 150,72
SOT223H\3P#2 [mil]
  rect 45x100 smd: 1(-91,-128) 2(0,-128) 3(91,-128)
  rect 283x250 smd far side: 4(0,42)
  rect 283x204 smd: 4(0,56)
  silkscreen extent -150,-53 150,72
SOT-23#1 [mil]
  rect 42x50 smd: 1(37.4,36) 2(-37.4,36) 3(0,-42.74)
  silkscreen extent -72,-76 72,72
SOT-23#2 [mil]
  rect 42x50 smd: 1(38.4,36) 2(-38.4,36) 3(0,-42.74)
  silkscreen extent -72,-76 72,72
SOT-89-1 [mil]
  rect 30x59.06 smd: 1(-57,-72) 2(0,-72) 3(57,-72)
  rect 154x126 smd: 4(0,39)
  silkscreen extent -85,-33 85,40
SW5P_EC11 [mm]
  oval 2.5x4 hole 1.5 slot 3 at 90 deg: 0(-5,0.25) 0(5,0.25)
  rect 1.6x1.6 hole 1: 1(-2.5,-7.5)
  round 1.6 hole 1: 2(0,-7.5) 3(2.5,-7.5) 4(2.5,7) 5(-2.5,7)
  silkscreen extent -15,-15 15,15
SW6-P2.54-Z8X8X12.5 [mil]
  rect 60x60 hole 40: 1(0,0)
  round 60 hole 40: 2(100,0) 3(200,0) 4(200,236.22) 5(100,236.22) 6(0,236.22)
  silkscreen extent -50,-50 250,300
SW-DIP4 [mil]
  rect 60x60 hole 37: 1(0,0)
  round 60 hole 37: 2(100,0) 3(200,0) 4(300,0) 5(300,300) 6(200,300) 7(100,300) 8(0,300)
  silkscreen extent -75,-70 375,350
SW-TACT-P4.5X6.5-Z6.2X6.2X5#1 [mil]
  rect 70x70 / inner rect 80x80 / far side rect 80x80 hole 40: 1(0,0)
  round 70 hole 40: 2(0,177) 4(256,177)
  oval 80x60 hole 40: 3(256,0)
  silkscreen extent 25,0 225,175
SW-TACT-P4.5X6.5-Z6.2X6.2X5#2 [mil]
  rect 70x70 / inner rect 80x80 / far side rect 80x80 hole 40: 1(0,0)
  round 80 hole 40: 2(0,177) 3(256,0) 4(256,177)
  silkscreen extent 25,0 225,175
SW-TACT-P4.5X6.5-Z6.2X6.2X5#3 [mil]
  rect 70x70 / inner rect 80x80 / far side rect 80x80 hole 40: 1(0,0)
  round 80 hole 40: 2(0,177)
  oval 65x80 hole 40: 3(256,0) 4(256,177)
  silkscreen extent 25,0 225,175
TPH60-COIL [mil]
  round 60 hole 40: 1(0,0)
  silkscreen extent -59,-59 59,59
USB5-MICRO-7.5.X5.4P065 [mm]
  rect 0.4x2.286 smd: 1(0,0)
  oval 0.4x2.286 smd: 2(0.65,0) 3(1.3,0) 4(1.95,0) 5(2.6,0)
  oval 1.5x1.905 hole 0.9 slot 1.27 at 90 deg: 6(4.6,-0.03)
  oval 3.556x2.286 hole 0.9 slot 1.778 at 90 deg copper offset 0.254,0: 7(4.9,-2.83)
  oval 3.302x2.286 / inner oval 3.556x2.286 / far side oval 3.556x2.286 hole 0.9 slot 1.778 at 90 deg copper offset -0.254,0: 8(-2.3,-2.83)
  rect 1.5x1.372 hole 0.9 slot 1.27 at 90 deg: 9(-2,-0.03)
  round 0.8 hole 0.914 unplated: 10(-0.65,-0.93) 11(3.25,-0.93)
  silkscreen extent -2.4,-5.43 5,0.25
XTAL-HC49US-G2 [mil]
  round 50 / inner round 50 / far side round 80 hole 37: 1(0,0) 2(200,0)
  rect 90x50 smd rot 135: 3(283,104)
  silkscreen extent -125,-100 325,100

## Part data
_DC_+5V1 _DC_GND1 TP1 TP2 TP3 TP4 TP5 TP6: library part TPH-GND
_ICKO1: library part TPH60-COIL
C1 C3 C5 C7 C9 C12 C14 C15 C17 C18 C20 C22 C24 C25 C27 C28 C29 C30 C32 C33 C34 C38 C39 C40 C41 C42 C51 C54 C55: library part CAP-NP
C2 C4 C6 C8 C10 C11 C13 C16 C19 C21 C23 C26 C31 C35 C36 C37: library part CAP-POL
C43 C44 C45 C46 C47 C48 C49 C50 C52 C53: library part CAP
CJ1: library part CJ-DC-JACK-3P
CN1: library part SIP6
CN2: library part SIP2-SPK
CN4 CN5 CN17 JP1 JP2 JP3: library part HEADER3
CN6: library part HEADER8
CN7: library part HEADER4
CN8: library part HEADER20X2A
CN9: library part HEADER17X2
CN10: library part HEADER14
CN11: library part HEADER11
CN14: library part SIP4
CN15 CN16: library part HEADER4X2
D1 D2 D3 D4 D7 D8 D9 D10: library part LED
D5 D6 D13: library part DIODE-SCHOTTKY-2
EC1 TC4 TC5: library part "CAP +"
F1: library part FUSE
FB1 FB6: library part FB+DIP
FB2 FB3 FB4 FB5 FB7 FB8 FB9 FB10 FB11 FB12 FB13 FB14 FB15: library part FB2
G1 G2 G3 G4: library part ScrewPad-9P, "MTG HOLE;ID2.5,OD6.6,NPTH,12 VIA"
G5: library part LOGO-Megawin_3_4
Q1: library part TRN-NPN-2N3904
Q2: library part MOS-N-SOT23
R1 R2 R3 R4 R5 R6 R7 R8 R9 R10 R11 R12 R13 R14 R15 R16 R17 R18 R19 R20 R21 R22 R23 R24 R25 R26 R27 R28 R29 R30 R31 R32 R33 R34 R35 R36 R37 R38 R39 R40 R41 R42 R43 R44 R45 R46 R47 R48 R49 R50 R51 R52 R53 R54 R55 R56 R57 R58 R59 R60 R61 R62 R63 R64 R65 R66 R67 R68 R69 R70 R71 R72 R73 R75 R78 R80 R81 R82 R83 R84 R85 R86 R87 R88 R89 R90 R91 R92 R93 R94 R95 R96 R97 R98 R99 R100 R101 R102 R103 R104 R105 R106 R107 R108 R109 R110 R111 R112 R113 R114 R115 R116 R117 R118 R119 R120 R121 R122 R123 R124 R125 R126 R127 R128 R129 R130 R131 R132 R133: library part R
R74 R76 R77 R79: library part R2X
RP1 RP2 RP3 RP4: library part RP4-SMD2
SW1: library part SW-PB-6P
SW2 SW4 SW5 SW6 SW7 SW8 SW9 SW10 SW11 SW12 SW14 SW15 SW16: library part SW-PB-4P
SW13: library part SW-EC11
SW17: library part SW-DIP4
TC1 TC2 TC3: library part CAP-EC
U1: library part IC-MG32F02U128-LQFP80
U3: library part ICM-24CXX
U4: library part ICM-25FXX
U5: library part ICM-25LXX
UP1: library part ICP-AP1115B
UP2 UP3: library part ICP-AP1117
X1: library part XTAL-G
Z1: library part DIODE-ZENER

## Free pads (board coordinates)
  round 157.48 hole 137.8: 1(3085.04,136.61)

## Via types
v1: diameter 25, hole 12, Top Layer to Bottom Layer, tented both sides, 253 vias
v2: diameter 25, hole 16, Top Layer to Bottom Layer, tented both sides, 83 vias
v3: diameter 20, hole 12, Top Layer to Bottom Layer, tented both sides, 77 vias
v4: diameter 35, hole 12, Top Layer to Bottom Layer, tented both sides, 64 vias
v5: diameter 40, hole 20, Top Layer to Bottom Layer, tented both sides, 16 vias
v6: diameter 30, hole 12, Top Layer to Bottom Layer, tented both sides, 13 vias
v7: diameter 28, hole 16, Top Layer to Bottom Layer, tented both sides, 2 vias

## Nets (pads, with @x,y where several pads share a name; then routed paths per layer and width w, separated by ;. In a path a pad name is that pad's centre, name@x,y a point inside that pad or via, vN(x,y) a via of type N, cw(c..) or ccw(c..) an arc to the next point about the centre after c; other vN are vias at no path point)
+5V: C4.1 C5.1 C8.1 C9.1 C11.1 FB2.1 FB7.1 FB9.1 JP1.3 JP2.3 JP3.1 R1.1 R67.2 SW1.2 SW1.5 UP1.2 UP1.4 UP3.3 Z1.2 | length 7478.8
  Top Layer w20: R1.1@4110,2535 4110,2630
  Top Layer w30: FB7.1@1895,3085 2386,3085 2586,3285 3220,3285 3270,3335 3378,3335 3500,3213 JP2.3@3500,3100 ; UP1.2@4445,2505 UP1.4@4556,2505
  Top Layer w40: v5@5007.7,2372.7 v5@5052.3,2372.7 ; UP3.3@5156,1090 C9.1@5300,1090 JP3.1@5300,800 ; v5@5277.7,1347.3 v5@5322.3,1347.3 ; R67.2@5310,650 JP3.1@5310,790
  Top Layer w50: v5@3793.19,2630 4110,2630 4485,2630 4556,2559 UP1.4@4556,2505 ; FB2.1@4555,2370 UP1.4@4555,2491 ; UP1.4@4585,2460 C5.1@4660,2460 4960,2460 ; C11.1@4915,2466 Z1.2@4915,2585 ; Z1.2@4920,2585 SW1.5@4920,2730 ; v5@5002.56,2377.7 v5@5002.56,2382.84 ; v5(5007.7,2377.7) v5@5002.56,2382.84 ; v5@5055,2380 4975,2460 4960,2460 ; v5(5277.7,1342.3) 5300,1320 ; C9.1@5300,1090 5300,1320 ; 5300,1330 5300,1320 ; v5(5322.3,1342.3) 5300,1320 ; 4960,2460 5002.56,2417.44 v5@5002.56,2382.84
  Bottom Layer w40: JP1.3@3500,2600 3500,2780 3570,2850 3570,3030 JP2.3@3500,3100 ; v5@5007.99,2382.69 v5@5052.04,2380.17 ; v5@5277.7,1337.3 v5@5322.3,1337.3 ; JP3.1@5300,800 5320,780 FB9.1@5320,670
  Bottom Layer w50: JP1.3@3510,2600 3780,2600 ; SW1.5@4920,2730 SW1.2@4920,2966.22 ; v5(5007.7,2377.7) 5007.7,2317.3 5052.04,2272.96 ; v5@5052.04,2377.44 5052.04,2272.96 ; v5(5277.7,1342.3) 5300,1364.6 ; v5(5322.3,1342.3) 5300,1364.6 ; 5052.04,2272.96 5300,2025 5300,1364.6
  other v5: 5052.3,2377.7 3782.7,2622.3
+5V_IN: _DC_+5V1.1 D5.2 D6.2 FB1.2 R4.1 SW1.3 SW1.6 TC2.1 | length 3035.6
  Top Layer w20: TC2.1@3954,3075 4025,3075 4030,3075 ; R4.1@4110,2930 4110,2929.59 4110.21,2929.79 4110.21,2969.79
  Top Layer w50: _DC_+5V1.1@3965,3465 3965,3240 ; D5.2@4059,3240 3965,3240 ; SW1.3@4820,2966.22 4133.78,2966.22 4025,3075 3965,3135 3965,3240 ; SW1.6@5020,2730 5020,2560 5201,2379 FB1.2@5695,2379
  Bottom Layer w50: SW1.3@4820,2966.22 4740,2886.22 4740,2690 4780,2650 4958.78,2650 5020,2711.22 SW1.6@5020,2730
+5V_LDO: C2.1 FB1.1 R5.1 UP2.2 UP2.4 | length 608.3
  Top Layer w50: UP2.4@5231,2510 UP2.4@5232,2510 ; UP2.4@5232,2549 UP2.4@5292,2549 ; UP2.4@5266,2645 v2(5292,2619) UP2.4@5371,2619 ; UP2.4@5372,2618 UP2.4@5371,2619 ; FB1.1@5689,2485 C2.1@5689,2583 ; C2.1@5689,2585 R5.1@5601,2585 5570,2585 5536,2619 UP2.2@5476,2619 v2(5373,2619) UP2.4@5371,2619
  other v2: 5213,2509 5293,2509 5373,2509 5208,2619 5208,2739 5293,2739 5373,2739
+5V_USB: C7.1 CJ2.1 CJ2.7 D5.1 | length 1145.1
  Top Layer w30: 4460,3345 4510,3295
  Top Layer w50: D5.1@4151,3240 4181,3270 4240,3270 4325,3355 4495,3355 4510,3370 ; CJ2.7@4583.78,3261.97 4540,3261.97 4510,3291.97 4510,3295 4510,3370 ; CJ2.1@4770,3160 4770,3360 4720,3410 4550,3410 4510,3370
+5V_USB2: C12.1 CJ3.1 CJ3.10 D6.1 | length 259.8
  Top Layer w45: C12.1@3726,3254 3740,3240 D6.1@3844,3240 ; C12.1@3726,3259 3726,3395
+12V: C3.1 F1.2 FB14.1 FB15.1 R2.1 TC1.1 UP2.3 | length 4720.9
  Top Layer w20: R2.1@4110,2730 4110,2830
  Top Layer w40: 1895,3170 2351,3170 2576,3395 v5(3175,3395) v5@3178.19,3395 ; 1895,3172 FB14.1@1895,3190 FB15.1@1895,3300
  Top Layer w50: 3780,2830 4110,2830 5055,2830 ; 5095,2830 5055,2830 ; UP2.3@5476,2710 C3.1@5601,2710 F1.2@5601,2957.7 ; TC1.1@5585,2830 5055,2830
  Bottom Layer w40: v5(3175,3395) 3350,3395 3757.6,2987.4 v5@3757.6,2840
  other v5: 3757.6,2825 3791.81,2860 3135,3355
+12V_JC: C1.1 CJ1.1 F1.1 | length 195
  Top Layer w50: CJ1.1@5353.7,3090 C1.1@5353.7,2975 F1.1@5433.7,2975
+12V_MX: CN4.3 FB15.2 | length 235
  Top Layer w30: CN4.3@1600,3300 FB15.2@1835,3300
+LCD_5V: C35.1 CN8.18 CN9.7 FB9.2 | length 3624.4
  Top Layer w20: 4650,135 4650,170 ; 4690,130 4685,135 4650,170 ; 4750,160 4750,250 CN9.7@4700,300 4650,250 4650,170
  Top Layer w32: CN8.18@3300,600 3235,665 3065,665 3030,630 3030,350 3320,60 4575,60 4650,135 4685,135 4725,135 4750,160
  Bottom Layer w30: CN9.7@4700,300 4770,370 5016,370 5256,610 FB9.2@5320,610
+LCD_BL: C37.1 CN8.19 CN9.10 CN9.11 FB10.2 Q2.2 R69.1 | length 4927.3
  Top Layer w20: 3150,435 3150,465 ; 3175,440 3150,465 ; 3250,460 3250,550 CN8.19@3200,600 3150,550 3150,465
  Top Layer w30: R69.1@1750,500 v5(1870,500)
  Top Layer w32: CN9.10@4600,190 CN9.10@4600,200 ; 5102.7,500 C37.1@5140,500 ; Q2.2@5210,506 FB10.2@5210,580
  Top Layer w40: 3160,440 3184.53,415.47 ; 3250,450 3250,415.47 ; CN9.11@4500,300 4500,325 4575,400 5002.7,400 5102.7,500 5108.7,506 C37.1@5130,506 Q2.2@5210,506 ; CN9.10@4600,190 4530,120 3360,120 3250,230 3250,350 ; C37.1@5154,506 Q2.2@5210,506 ; Q2.2@5222.6,506 Q2.2@5221.6,506 Q2.2@5210,506 ; 3184.53,415.47 3250,350 ; 3184.53,415.47 3250,415.47 ; 3250,350 3250,415.47
  Bottom Layer w20: CN8.19@3200,600 CN8.19@3200,605
  Bottom Layer w40: v5@1870,495 2885,495 3061,671 3154,671 CN8.19@3200,625 ; CN8.19@3200,600 CN8.19@3200,620 ; CN9.11@4500,300 CN9.10@4600,200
